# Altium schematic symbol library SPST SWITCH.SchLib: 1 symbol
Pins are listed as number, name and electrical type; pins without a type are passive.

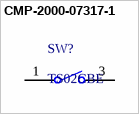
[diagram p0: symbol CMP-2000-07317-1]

## CMP-2000-07317-1
designator SW?, comment TS02CBE
Tiny Slide Switch, SPST, 20 V, -30 to 85 degC, 2-Pin THD, RoHS, Bulk; Manufacturer: C&K Components; Product Height (mm): 12.91mm; Actuator Style: TopSlide; Product Length (mm): 10.16mm; Switch Configuration: OFFNoneON; AC Voltage Rating (Max): 20V; Product Depth (mm): 5.08mm; Actuator Material: Nylon
footprint CKCP-TS02CBE_V (THD, 2-Leads, Body 10.16x5.08mm)
pins: 1, 3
